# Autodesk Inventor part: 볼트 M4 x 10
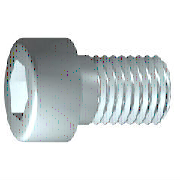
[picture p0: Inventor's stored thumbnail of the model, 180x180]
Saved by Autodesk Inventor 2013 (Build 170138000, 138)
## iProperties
IsCustomPart: 0
Created: 2012-02
Part Number: 볼트 M4 x 10
Material: 스테인리스강
Description: 6각 소켓 머리 캡 나사
Document SubType Name: Modeling
Standard: ISO 4762
Designer: mduedu
Standard Revision: Fourth edition 2004-03-01
Standards Organization: ISO
Language: ko-KR
Size Designation: M4 x 10
Categories: <MemberInstance><Categories><Category DisplayName="조임쇠" InternalName="e4da775c-781d-43d5-af7c-5136215cf5a6" Mnemonic="FSTN"><Category DisplayName="볼트" InternalN
Density: 8.08 g/cm^3
Author: mduedu
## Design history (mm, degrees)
sketch "스케치1"
  geometry: L1 (-1, 0)-(10, 0); L2 (10, 0)-(10, 2); L3 (10, 2)-(1.75, 2); L4 (1.75, 2)-(1.32, 2); L5 (1.32, 2)-(0, 2); L6 (0, 2)-(0, 3.5); L7 (0, 3.5)-(-4, 3.5); L8 (-4, 3.5)-(-4, 1.732); L9 (-4, 1.732)-(-2, 1.732); L10 (-2, 1.732)-(-1, 0); L11 (-6.8, 0)-(12.8, 0) reference; L12 (0, -0.7)-(0, 4.2) reference; L13 (1.75, 2)-(0, 2)
  constraints: 22 end point, 6 parallel, 2 collinear, 2 perpendicular, 1 horizontal, 1 point on line
  dimensions: "d1" = 8.25 distance from line of L3.end L2 (= GEL); "d2" = 0.42952 distance of L4.end L3.end (computed from GAL); "d3" = 4 distance between parallel lines of L8 L6 (= KOH); "d4" = 2 distance of L8.end L9.end (= INTI); "d5" = 60 deg angle of L10 L1; "d6" = 4 diameter of L3 L1 (= GD); "d7" = 4 diameter of L5 L1 (= BDM); "d8" = 3.4641 diameter of L9 L1 (= 1.1547 x SW); "d9" = 7 diameter of L7 L1 (= KOD); "d26" = 10 distance between parallel lines of L12 L2 (= NLG)
revolve "본체" sketch "스케치1" stored, may be unused: angle "d10" = 90 deg
sketch "스케치2"
  geometry: L1 (0, -4.9)-(0, 4.9) reference; L2 (-4.9, 0)-(4.9, 0) reference; L3 (1.732, 0)-(0.866, -1.5); L4 (0.866, -1.5)-(-0.866, -1.5); L5 (-0.866, -1.5)-(-1.732, 0); L6 (-1.732, 0)-(-0.866, 1.5); L7 (-0.866, 1.5)-(0.866, 1.5); L8 (0.866, 1.5)-(1.732, 0); 2 further points
  constraints: 12 end point, 1 coincident, 1 horizontal alignment, 1 point on line, 12 other
extrude "슬롯" join sketch "스케치2" stored distance "d11" = 10; taper "d12" = 0 deg
workplane "Work Plane1"
fillet "Fillet2" dims "d30" = 0.1 (= R)
body "Solid1"
fillet "모깎기1" dims "d17" = 0.4 (= RR)
feature "스레드" dims "d13" = 8.25 (= GEL), "d14" = 0
chamfer "모따기1" distance "d15" = 0.42941 (= -0.5 x SPD + 0.5 x GD); stored, may be unused: second distance "d16" = 0.42941 (= GUL), angle "d27" = 45 deg
other parameters: "GD" = 4 [user parameter; used in 2 equation terms], "NLG" = 10 [user parameter; used in 1 equation term], "GEL" = 8.25 [user parameter; used in 2 equation terms], "KOD" = 7 [user parameter; used in 1 equation term], "KOH" = 4 [user parameter; used in 1 equation term], "INTI" = 2 [user parameter; used in 1 equation term], "GAL" = 0.42941 (= 0.61345 x PTC) [user parameter; used in 1 equation term], "GUL" = 0.42941 (= 0.61345 x PTC) [user parameter; used in 1 equation term], "BDM" = 4 (= NND) [user parameter; used in 1 equation term], "SW" = 3 [user parameter; used in 2 equation terms], "RR" = 0.4 [user parameter; used in 1 equation term], "SPD" = 3.14117 (= NND - 1.2269 x PTC) [user parameter; used in 1 equation term], "d19" = 0, "d28" = 0, "d29" = 0, "R" = 0.1 [user parameter; used in 1 equation term], "TOA" = 30 deg [user parameter], "GD1" = 3.14117 (= THREADDIA - 1.2269 x PTC) [user parameter], "THREADDIA" = 4 [user parameter; used in 1 equation term], "FAWI" = 45 deg [user parameter], "TPU" = 14.28571 (computed from PTC) [user parameter], "PTC" = 0.7 [user parameter; used in 5 equation terms], "NND" = 4 [user parameter; used in 2 equation terms], "E0" = 3.465 (= 1.155 x SW) [user parameter]
